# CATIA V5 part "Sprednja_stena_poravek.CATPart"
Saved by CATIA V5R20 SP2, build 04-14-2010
Part number: Sprednja_stena
Bounding box of the stored display mesh (mm): x -23.1 to 23.1, y -17.5 to 17.5, z 0 to 6
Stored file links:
  C:\Documents and Settings\Administrator\My Documents\Hobi_dokumenti\CAD_CNC\Clap_CATIA\Sprednja_stena_poravek.CATPart
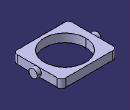
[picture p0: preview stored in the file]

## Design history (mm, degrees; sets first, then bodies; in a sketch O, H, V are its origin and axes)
Body1 (main body)
  Sketch1 on xy-plane, origin (0, 0, 0), H (1, 0, 0), V (0, 1, 0)
    point P1 (-20, 17.5)
    line L1 (-20, 17.5) -> (20, 17.5)
    line L2 (20, 17.5) -> (20, -17.5)
    line L3 (20, -17.5) -> (-20, -17.5)
    line L4 (-20, -17.5) -> (-20, 17.5)
    reference intersected line E2 through (0, 0) direction (0, 1) from yz-plane
    reference intersected line E3 through (0, 0) direction (-1, 0) from zx-plane
    circle A1 centre (0, 0) radius 15
    distance L1 L3 = 35
    distance L2 L4 = 40
    distance E3 L1 = 17.5
    distance P1 E2 = 20
    radius A1 = 15
    horizontal: L1 H, L3 H, E3 H
    vertical: L2 V, L4 V, E2 V
    perpendicularity: E2 L1
  Pad1: profile Sketch1, direction (0, 0, 1), length 6
  Sketch2 on face of Pad1 from Sketch1.L2, origin (20, 0, 0), H (0, 1, 0), V (0, 0, 1)
    circle A1 centre (0, 3) radius 3
    point P1 (0, 3)
    reference intersected line E1 through (0, 0) direction (-1, 0) from xy-plane
    reference intersected line E2 through (0, 0) direction (0, 1) from zx-plane
    distance P1 E1 = 3
    distance P1 E2 = 0
    radius A1 = 3
    vertical: E2 V
    horizontal: E1 H
  Pad2: profile Sketch2, direction (1, 0, 0), length 3.1
  Mirror1: of Pad2, Sketch2, about yz-plane
  Fillet1: radius 3, on edge [face of Pad1 from Sketch1.L4 | face of Pad1 from Sketch1.L1]; edge [face of Pad1 from Sketch1.L1 | face of Pad1 from Sketch1.L2]; edge [face of Pad1 from Sketch1.L3 | face of Pad1 from Sketch1.L4]; edge [face of Pad1 from Sketch1.L2 | face of Pad1 from Sketch1.L3]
